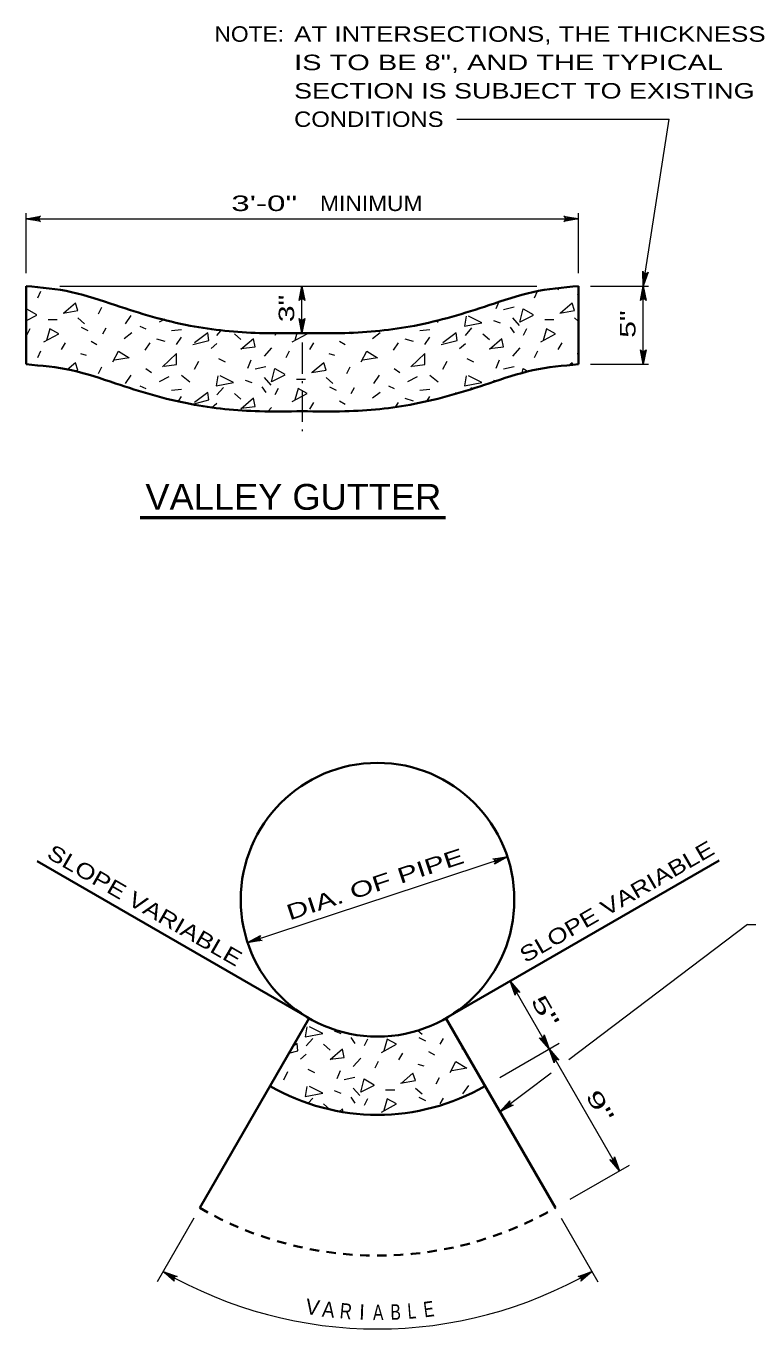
# Model space of a CAD drawing. Extents: x -10 to 104, y -162 to -1.
# Drawn here: x -10.5 to 35.7, y -84.5 to -1.2 of the extents above; entities that cross this region are included whole.
import ezdxf
from ezdxf.enums import TextEntityAlignment as Align

# ---------------------------------------------------------------- set-up
doc = ezdxf.new("R2010")
doc.units = 0
doc.header["$LTSCALE"] = 0.4
doc.linetypes.add('DOT_DASHED', pattern=[7.7, 5, -1.2, 0.3, -1.2])
doc.linetypes.add('SHORT_DASHED', pattern=[2.7, 1.5, -1.2])
for name, color, linetype, lineweight in [('1', 7, 'Continuous', 35), ('10', 7, 'Continuous', 13), ('12', 7, 'Continuous', 53), ('6', 7, 'Continuous', 13)]:
    doc.layers.add(name, color=color, linetype=linetype, lineweight=lineweight)
doc.layers.add('13', color=7, linetype='Continuous')

msp = doc.modelspace()

# ---------------------------------------------------------------- linework, layer by layer
at = {"layer": '1'}
for p, q in [((-10.4681, -17.8014), (-10.4681, -22.8014)), ((24.8652, -17.8014), (24.8652, -22.8014)), ((7.638, -64.6102), (-9.7541, -54.5688)), ((16.388, -64.6102), (33.856, -54.5251)), ((7.638, -64.6102), (0.638, -76.7346)), ((16.388, -64.6102), (23.388, -76.7346))]:
    msp.add_line(p, q, dxfattribs=at)
at = {"layer": '1', "lineweight": 13}
for p, q in [((-6.9918, -18.3044), (-6.6211, -18.4103)), ((6.352, -25.7705), (6.3355, -25.8034)), ((10.8561, -65.7014), (10.8893, -65.7387)), ((13.6282, -70.6866), (13.6428, -70.6632))]:
    msp.add_line(p, q, dxfattribs=at)
for points in [[(17.0503, -24.6252), (17.0481, -24.6056), (17.0049, -24.638), (17.0049, -24.6381)], [(5.1706, -68.9158), (5.3515, -69.0606), (5.3515, -69.0606)]]:
    msp.add_lwpolyline(points, dxfattribs=at)
at = {"layer": '1'}
msp.add_circle((12.013, -57.0325), 8.75, dxfattribs=at)
msp.add_arc((12.013, -57.0325), 13.75, 240, 299.99999, dxfattribs=at)
at = {"layer": '1', "linetype": 'SHORT_DASHED'}
msp.add_arc((12.013, -57.0325), 22.75, 240, 299.99999, dxfattribs=at)
at = {"layer": '1'}
for points in [[(-10.4681, -17.8014), (-7.5503, -18.1833), (-4.7439, -19.0256), (0.0268, -20.336), (4.4702, -20.804), (7.1985, -20.8014)], [(24.8652, -17.8014), (21.9474, -18.1833), (19.141, -19.0256), (14.3702, -20.336), (9.9268, -20.804), (7.1985, -20.8014)], [(-10.4681, -22.8014), (-7.5503, -23.1833), (-4.7439, -24.0256), (0.0268, -25.336), (4.4702, -25.804), (7.1985, -25.8014)], [(24.8652, -22.8014), (21.9474, -23.1833), (19.141, -24.0256), (14.3702, -25.336), (9.9268, -25.804), (7.1985, -25.8014)]]:
    msp.add_spline(points, degree=3, dxfattribs=at)
at = {"layer": '10'}
for p, q in [((17.0886, -7.1328), (30.6672, -7.1328)), ((29.0141, -17.8014), (30.6672, -7.1328)), ((-10.4681, -16.9665), (-10.4681, -13.1495)), ((24.8652, -16.9665), (24.8652, -13.1495)), ((-10.4681, -13.5034), (24.8652, -13.5034)), ((-8.2987, -17.8014), (22.197, -17.8014)), ((7.1827, -20.8014), (7.1799, -17.8014)), ((25.6465, -17.8014), (29.3415, -17.8014)), ((29.0141, -22.8014), (29.0141, -17.8014)), ((25.6465, -22.8014), (29.3415, -22.8014)), ((3.7017, -59.7683), (20.3243, -54.2966)), ((35.6689, -58.6171), (24.2525, -67.2602)), ((35.6689, -58.6171), (51.1348, -58.6171)), ((19.8445, -68.3881), (23.6283, -66.2036)), ((23.1261, -68.1131), (19.8447, -70.5973)), ((24.3445, -76.1824), (28.1283, -73.9978)), ((0.2607, -77.3881), (-2.0887, -81.4574)), ((23.7653, -77.3881), (26.1148, -81.4574))]:
    msp.add_line(p, q, dxfattribs=at)
at = {"layer": '10', "linetype": 'DOT_DASHED'}
msp.add_line((7.1985, -21.4098), (7.2039, -27.0776), dxfattribs=at)
at = {"layer": '10'}
for points in [[(-10.4681, -13.5034), (-9.5361, -13.3286), (-9.6079, -13.3784), (-9.6449, -13.4409), (-9.6556, -13.5034), (-9.6449, -13.5659), (-9.6079, -13.6284), (-9.5361, -13.6781), (-10.4681, -13.5034), (-9.6079, -13.6284), (-9.6449, -13.5659), (-10.4681, -13.5034), (-9.6556, -13.5034), (-9.6449, -13.4409), (-10.4681, -13.5034), (-9.6079, -13.3784)], [(24.8652, -13.5034), (23.9331, -13.6781), (24.0049, -13.6284), (24.042, -13.5659), (24.0527, -13.5034), (24.042, -13.4409), (24.0049, -13.3784), (23.9331, -13.3286), (24.8652, -13.5034), (24.0049, -13.3784), (24.042, -13.4409), (24.8652, -13.5034), (24.0527, -13.5034), (24.042, -13.5659), (24.8652, -13.5034), (24.0049, -13.6284)], [(29.0141, -17.8014), (28.9841, -16.8536), (29.0223, -16.9322), (29.0784, -16.9783), (29.1385, -16.9985), (29.2019, -16.9975), (29.2693, -16.9704), (29.3295, -16.9071), (29.0141, -17.8014), (29.2693, -16.9704), (29.2019, -16.9975), (29.0141, -17.8014), (29.1385, -16.9985), (29.0784, -16.9783), (29.0141, -17.8014), (29.0223, -16.9322)], [(7.1799, -17.8014), (7.3555, -18.7333), (7.3057, -18.6615), (7.2432, -18.6246), (7.1806, -18.6139), (7.1182, -18.6247), (7.0557, -18.6618), (7.006, -18.7336), (7.1799, -17.8014), (7.0557, -18.6618), (7.1182, -18.6247), (7.1799, -17.8014), (7.1806, -18.6139), (7.2432, -18.6246), (7.1799, -17.8014), (7.3057, -18.6615)], [(29.0141, -17.8014), (29.1889, -18.7335), (29.1391, -18.6617), (29.0766, -18.6246), (29.0141, -18.6139), (28.9516, -18.6246), (28.8891, -18.6617), (28.8393, -18.7335), (29.0141, -17.8014), (28.8891, -18.6617), (28.9516, -18.6246), (29.0141, -17.8014), (29.0141, -18.6139), (29.0766, -18.6246), (29.0141, -17.8014), (29.1391, -18.6617)], [(7.1827, -20.8014), (7.0071, -19.8695), (7.0569, -19.9413), (7.1194, -19.9783), (7.1819, -19.9889), (7.2444, -19.9781), (7.3069, -19.9411), (7.3566, -19.8692), (7.1827, -20.8014), (7.3069, -19.9411), (7.2444, -19.9781), (7.1827, -20.8014), (7.1819, -19.9889), (7.1194, -19.9783), (7.1827, -20.8014), (7.0569, -19.9413)], [(29.0141, -22.8014), (28.8393, -21.8693), (28.8891, -21.9412), (28.9516, -21.9782), (29.0141, -21.9889), (29.0766, -21.9782), (29.1391, -21.9412), (29.1889, -21.8693), (29.0141, -22.8014), (29.1391, -21.9412), (29.0766, -21.9782), (29.0141, -22.8014), (29.0141, -21.9889), (28.9516, -21.9782), (29.0141, -22.8014), (28.8891, -21.9412)], [(20.3243, -54.2966), (19.4936, -54.7541), (19.5463, -54.6844), (19.5619, -54.6134), (19.5526, -54.5507), (19.5229, -54.4947), (19.4681, -54.4469), (19.3844, -54.4221), (20.3243, -54.2966), (19.4681, -54.4469), (19.5229, -54.4947), (20.3243, -54.2966), (19.5526, -54.5507), (19.5619, -54.6134), (20.3243, -54.2966), (19.5463, -54.6844)], [(3.7017, -59.7683), (4.5324, -59.3109), (4.4798, -59.3806), (4.4641, -59.4516), (4.4735, -59.5143), (4.5032, -59.5703), (4.5579, -59.6181), (4.6417, -59.6429), (3.7017, -59.7683), (4.5579, -59.6181), (4.5032, -59.5703), (3.7017, -59.7683), (4.4735, -59.5143), (4.4641, -59.4516), (3.7017, -59.7683), (4.4798, -59.3806)], [(27.4926, -74.3648), (22.9926, -66.5706), (20.4926, -62.2405)], [(20.4926, -62.2405), (21.1099, -62.9603), (21.0309, -62.923), (20.9583, -62.9221), (20.8988, -62.9441), (20.85, -62.9846), (20.8144, -63.048), (20.8072, -63.1351), (20.4926, -62.2405), (20.8144, -63.048), (20.85, -62.9846), (20.4926, -62.2405), (20.8988, -62.9441), (20.9583, -62.9221), (20.4926, -62.2405), (21.0309, -62.923)], [(22.9926, -66.5706), (22.3752, -65.8508), (22.4542, -65.8881), (22.5268, -65.8889), (22.5863, -65.8669), (22.6351, -65.8264), (22.6707, -65.7631), (22.6779, -65.676), (22.9926, -66.5706), (22.6707, -65.7631), (22.6351, -65.8264), (22.9926, -66.5706), (22.5863, -65.8669), (22.5268, -65.8889), (22.9926, -66.5706), (22.4542, -65.8881)], [(22.9926, -66.5706), (23.6099, -67.2904), (23.5309, -67.2531), (23.4583, -67.2523), (23.3988, -67.2742), (23.35, -67.3148), (23.3144, -67.3781), (23.3072, -67.4652), (22.9926, -66.5706), (23.3144, -67.3781), (23.35, -67.3148), (22.9926, -66.5706), (23.3988, -67.2742), (23.4583, -67.2523), (22.9926, -66.5706), (23.5309, -67.2531)], [(19.8447, -70.5973), (20.4823, -69.8954), (20.4551, -69.9784), (20.4633, -70.0506), (20.4925, -70.1069), (20.5388, -70.1502), (20.606, -70.1777), (20.6933, -70.174), (19.8447, -70.5973), (20.606, -70.1777), (20.5388, -70.1502), (19.8447, -70.5973), (20.4925, -70.1069), (20.4633, -70.0506), (19.8447, -70.5973), (20.4551, -69.9784)], [(27.4926, -74.3648), (26.8752, -73.645), (26.9542, -73.6823), (27.0268, -73.6831), (27.0863, -73.6612), (27.1351, -73.6206), (27.1707, -73.5573), (27.1779, -73.4702), (27.4926, -74.3648), (27.1707, -73.5573), (27.1351, -73.6206), (27.4926, -74.3648), (27.0863, -73.6612), (27.0268, -73.6831), (27.4926, -74.3648), (26.9542, -73.6823)], [(-1.7064, -80.7953), (-0.8119, -81.11), (-0.899, -81.1172), (-0.9623, -81.1528), (-1.0028, -81.2016), (-1.0248, -81.2611), (-1.024, -81.3337), (-0.9866, -81.4127), (-1.7064, -80.7953), (-1.024, -81.3337), (-1.0248, -81.2611), (-1.7064, -80.7953), (-1.0028, -81.2016), (-0.9623, -81.1528), (-1.7064, -80.7953), (-0.899, -81.1172)], [(25.7325, -80.7953), (25.0127, -81.4127), (25.05, -81.3337), (25.0509, -81.2611), (25.0289, -81.2016), (24.9884, -81.1528), (24.925, -81.1172), (24.838, -81.11), (25.7325, -80.7953), (24.925, -81.1172), (24.9884, -81.1528), (25.7325, -80.7953), (25.0289, -81.2016), (25.0509, -81.2611), (25.7325, -80.7953), (25.05, -81.3337)]]:
    msp.add_lwpolyline(points, dxfattribs=at)
msp.add_arc((12.013, -57.0325), 27.439, 240, 300, dxfattribs=at)
at = {"layer": '12'}
msp.add_line((-3.1772, -32.6017), (16.3578, -32.6017), dxfattribs=at)
at = {"layer": '6'}
for p, q in [((-9.5335, -18.1455), (-9.7453, -18.5691)), ((22.2353, -18.1497), (22.0256, -18.5691)), ((23.5611, -18.0396), (23.6071, -17.9661)), ((24.779, -18.3044), (24.8344, -18.3202)), ((-5.8269, -19.5752), (-5.6151, -19.1516)), ((19.7676, -18.8131), (19.5898, -19.2575)), ((20.7547, -19.1516), (20.0664, -19.3105)), ((-9.7982, -19.6811), (-10.4681, -20.0161)), ((-9.0569, -19.9459), (-8.4744, -19.9459)), ((-7.1506, -19.84), (-6.727, -20.2106)), ((-3.7617, -19.6811), (-4.1324, -20.2106)), ((-1.5885, -19.9183), (-1.9614, -20.1047)), ((15.7351, -19.9862), (15.8832, -20.1047)), ((20.6488, -19.84), (21.0725, -20.3165)), ((22.7139, -19.9459), (23.2964, -19.9459)), ((24.6202, -19.84), (24.8462, -20.0378)), ((-10.2218, -20.5284), (-10.4336, -20.952)), ((-6.9389, -20.4224), (-6.5152, -20.6342)), ((-5.5621, -20.8461), (-5.3503, -20.4754)), ((-3.7088, -20.7931), (-4.1854, -21.1638)), ((-3.1793, -20.3695), (-2.8086, -20.5284)), ((-1.1671, -20.6342), (-0.5317, -20.5813)), ((1.7452, -20.952), (1.9965, -20.6692)), ((5.5263, -20.803), (5.4518, -20.952)), ((6.8563, -20.8017), (6.7226, -21.2697)), ((10.3233, -20.8461), (10.3508, -20.798)), ((12.1766, -20.7931), (11.7, -21.1638)), ((14.7183, -20.6342), (15.3537, -20.5813)), ((17.6306, -20.952), (18.0542, -20.4754)), ((19.431, -19.9988), (19.8546, -20.1577)), ((20.49, -20.4224), (20.7547, -20.7931)), ((21.549, -20.5284), (21.3372, -20.952)), ((24.832, -20.4224), (24.8489, -20.4309)), ((-8.2097, -21.8521), (-7.9449, -21.4285)), ((-6.3034, -21.3226), (-5.9328, -21.5344)), ((-2.5439, -21.4285), (-2.8616, -21.9051)), ((-2.1203, -21.1638), (-1.5907, -21.3226)), ((-0.8494, -21.5344), (-0.5317, -21.0579)), ((1.3745, -21.7992), (1.7452, -21.4815)), ((2.8572, -20.8461), (3.2808, -21.2167)), ((7.6757, -21.8521), (7.9405, -21.4285)), ((9.582, -21.3226), (9.9526, -21.5344)), ((13.3415, -21.4285), (13.0238, -21.9051)), ((13.7651, -21.1638), (14.2947, -21.3226)), ((15.036, -21.5344), (15.3537, -21.0579)), ((17.2599, -21.7992), (17.6306, -21.4815)), ((18.7426, -20.8461), (19.1662, -21.2167)), ((23.5611, -21.8521), (23.8259, -21.4285)), ((-9.5335, -21.958), (-9.7453, -22.3816)), ((-6.9918, -22.1169), (-6.6211, -22.2228)), ((1.8511, -22.4346), (2.2747, -22.6464)), ((5.24, -21.7462), (4.7634, -22.2757)), ((6.352, -21.958), (6.1401, -22.3816)), ((8.8936, -22.1169), (9.2643, -22.2228)), ((17.7365, -22.4346), (18.1601, -22.6464)), ((21.1254, -21.7462), (20.6488, -22.2757)), ((22.2374, -21.958), (22.0256, -22.3816)), ((24.779, -22.1169), (24.8607, -22.1402)), ((-5.8269, -23.3877), (-5.6151, -22.9641)), ((-2.8086, -23.07), (-2.438, -23.3348)), ((0.3155, -23.123), (0.5802, -22.5935)), ((3.9162, -22.5405), (3.7044, -23.07)), ((4.8693, -22.9641), (4.181, -23.123)), ((10.0586, -23.3877), (10.2704, -22.9641)), ((13.0768, -23.07), (13.4474, -23.3348)), ((16.2009, -23.123), (16.4657, -22.5935)), ((19.8016, -22.5405), (19.5898, -23.07)), ((20.7547, -22.9641), (20.0664, -23.123)), ((-3.7617, -23.4936), (-4.1324, -24.0231)), ((-1.326, -23.5995), (-1.9614, -23.9172)), ((-0.5317, -23.4936), (-0.0022, -23.9172)), ((3.5455, -23.8113), (3.9691, -23.9702)), ((4.7634, -23.6525), (5.187, -24.129)), ((6.8285, -23.7584), (7.411, -23.7584)), ((8.7348, -23.6525), (9.1584, -24.0231)), ((12.1237, -23.4936), (11.753, -24.0231)), ((14.5594, -23.5995), (13.924, -23.9172)), ((15.3537, -23.4936), (15.8832, -23.9172)), ((19.431, -23.8113), (19.5977, -23.8739)), ((-3.1793, -24.182), (-2.8086, -24.3409)), ((-1.1671, -24.4467), (-0.5317, -24.3938)), ((-0.7177, -25.1494), (-0.5317, -24.8704)), ((1.7452, -24.7645), (2.1688, -24.2879)), ((2.8572, -24.6586), (3.2808, -25.0292)), ((4.6046, -24.2349), (4.8693, -24.6056)), ((5.6636, -24.3409), (5.4518, -24.7645)), ((8.9466, -24.2349), (9.3702, -24.4467)), ((10.3233, -24.6586), (10.5351, -24.2879)), ((12.1766, -24.6056), (11.7, -24.9763)), ((12.7061, -24.182), (13.0768, -24.3409)), ((13.7651, -24.9763), (14.2947, -25.1351)), ((14.7183, -24.4467), (15.3537, -24.3938)), ((15.1801, -25.1308), (15.3537, -24.8704)), ((17.994, -24.3556), (18.0542, -24.2879)), ((1.3945, -25.5946), (1.7452, -25.294)), ((5.24, -25.5587), (5.0197, -25.8035)), ((7.6757, -25.6646), (7.9405, -25.241)), ((9.582, -25.1351), (9.9526, -25.3469)), ((13.3415, -25.241), (13.1234, -25.5683)), ((15.7608, -64.9974), (15.8008, -64.9175)), ((9.2478, -65.421), (9.6714, -65.5799)), ((14.5883, -65.3946), (14.8607, -65.6329)), ((7.4475, -66.3742), (7.8711, -65.8976)), ((8.5594, -66.2683), (8.9831, -66.6389)), ((10.3068, -65.8446), (10.5716, -66.2153)), ((11.3659, -65.9506), (11.1541, -66.3742)), ((14.6488, -65.8446), (15.0725, -66.0565)), ((16.0256, -66.2683), (16.2374, -65.8976)), ((17.4896, -66.5181), (17.4023, -66.586)), ((7.0768, -67.2214), (7.4475, -66.9037)), ((10.9423, -67.1684), (10.4657, -67.698)), ((12.0542, -67.3803), (11.8424, -67.8039)), ((13.378, -67.2743), (13.6428, -66.8507)), ((15.2843, -66.7448), (15.6549, -66.9566)), ((6.0178, -68.5452), (6.2825, -68.0157)), ((7.5534, -67.8568), (7.977, -68.0686)), ((9.6185, -67.9627), (9.4067, -68.4922)), ((14.5959, -67.5391), (14.9666, -67.645)), ((10.5716, -68.3863), (9.8832, -68.5452)), ((10.4657, -69.0747), (10.8893, -69.5512)), ((14.4371, -69.0747), (14.8607, -69.4454)), ((15.7608, -68.8099), (15.9726, -68.3863)), ((17.8259, -68.9158), (17.4553, -69.4454)), ((7.5748, -70.0434), (7.8711, -69.7101)), ((9.2478, -69.2335), (9.6714, -69.3924)), ((10.3068, -69.6571), (10.5716, -70.0278)), ((11.3659, -69.7631), (11.1541, -70.1867)), ((12.5308, -69.1806), (13.1133, -69.1806)), ((14.6488, -69.6571), (15.0725, -69.869)), ((16.0256, -70.0808), (16.2374, -69.7101)), ((8.5594, -70.0808), (8.9707, -70.4406))]:
    msp.add_line(p, q, dxfattribs=at)
for points in [[(-8.1038, -19.5223), (-7.1506, -19.3634), (-7.3095, -18.8869), (-8.0508, -19.5223)], [(23.6671, -19.5223), (24.6202, -19.3634), (24.4613, -18.8869), (23.72, -19.5223)], [(-10.4681, -19.3955), (-10.4336, -19.2575), (-9.7982, -19.6282)], [(17.6836, -19.7341), (17.5776, -20.3695), (18.6896, -20.1577), (17.8424, -19.7341)], [(21.9726, -19.6811), (21.1254, -20.1047), (21.3372, -19.2575), (21.9726, -19.6282)], [(-9.3217, -21.3756), (-8.3685, -20.8461), (-8.951, -20.5284), (-9.1628, -21.2697)], [(0.2096, -21.5344), (1.2157, -21.2697), (1.1627, -20.7931), (0.3155, -21.4285)], [(6.5637, -21.3756), (7.5169, -20.8461), (7.4357, -20.8018)], [(16.095, -21.5344), (17.1011, -21.2697), (17.0481, -20.7931), (16.2009, -21.4285)], [(22.4492, -21.3756), (23.4023, -20.8461), (22.8198, -20.5284), (22.608, -21.2697)], [(3.2808, -21.7992), (4.181, -21.6933), (4.0751, -21.1638), (3.2808, -21.8521)], [(19.1662, -21.7992), (20.0664, -21.6933), (19.9605, -21.1638), (19.1662, -21.8521)], [(-4.9267, -22.6464), (-4.556, -21.958), (-3.8677, -22.3816), (-4.8208, -22.5405)], [(-1.6437, -22.9112), (-0.8494, -22.8053), (-0.8494, -22.1169), (-1.7496, -22.9641)], [(10.9587, -22.6464), (11.3294, -21.958), (12.0177, -22.3816), (11.0646, -22.5405)], [(14.2417, -22.9112), (15.036, -22.8053), (15.036, -22.1169), (14.1358, -22.9641)], [(-7.4005, -23.2176), (-7.1506, -23.1759), (-7.3095, -22.6994), (-7.8312, -23.1465)], [(6.0872, -23.4936), (5.24, -23.9172), (5.4518, -23.07), (6.0872, -23.4407)], [(7.7816, -23.3348), (8.7348, -23.1759), (8.5759, -22.6994), (7.8346, -23.3348)], [(21.2739, -23.3231), (21.3372, -23.07), (21.6496, -23.2523)], [(24.5108, -22.8478), (24.4613, -22.6994), (24.248, -22.8822)], [(1.7981, -23.5466), (1.6922, -24.182), (2.8042, -23.9702), (1.957, -23.5466)], [(17.6836, -23.5466), (17.5776, -24.182), (18.6896, -23.9702), (17.8424, -23.5466)], [(0.2096, -25.3469), (1.2157, -25.0822), (1.1627, -24.6056), (0.3155, -25.241)], [(3.2808, -25.6117), (4.181, -25.5058), (4.0751, -24.9763), (3.2808, -25.6646)], [(6.5637, -25.1881), (7.5169, -24.6586), (6.9344, -24.3409), (6.7226, -25.0822)], [(7.5004, -65.1563), (7.3945, -65.7917), (8.5065, -65.5799), (7.6593, -65.1563)], [(6.3499, -66.8414), (6.9179, -66.6919), (6.865, -66.2153), (6.594, -66.4186)], [(8.9831, -67.2214), (9.8832, -67.1155), (9.7773, -66.586), (8.9831, -67.2743)], [(12.266, -66.7978), (13.2192, -66.2683), (12.6367, -65.9506), (12.4249, -66.6919)], [(16.661, -68.0686), (17.0317, -67.3803), (17.72, -67.8039), (16.7669, -67.9627)], [(13.4839, -68.757), (14.4371, -68.5981), (14.2782, -68.1216), (13.5369, -68.757)], [(7.5004, -68.9688), (7.3945, -69.6042), (8.5065, -69.3924), (7.6593, -68.9688)], [(11.7895, -68.9158), (10.9423, -69.3394), (11.1541, -68.4922), (11.7895, -68.8629)], [(12.266, -70.6103), (13.2192, -70.0808), (12.6367, -69.7631), (12.4249, -70.5044)], [(9.8188, -70.6056), (9.7773, -70.3985), (9.5855, -70.5648)]]:
    msp.add_lwpolyline(points, dxfattribs=at)

# ---------------------------------------------------------------- texts
at = {"layer": '12'}
for s, width, p in [('NOTE:', 1.1, (1.5841, -2.1828)), ('AT INTERSECTIONS, THE THICKNESS', 1.25, (6.6796, -2.1828)), ('IS TO BE 8", AND THE TYPICAL', 1.4, (6.6796, -3.9978)), ('SECTION IS SUBJECT TO EXISTING', 1.3, (6.6796, -5.8128)), ('CONDITIONS', 1.15, (6.6796, -7.6278))]:
    msp.add_text(s, height=0.99, dxfattribs=dict(at, width=width)).set_placement(p)
for s, height, width, p in [('MINIMUM', 0.99, 1.1, (11.613, -13.0034)), ('VALLEY GUTTER', 1.65, 1.05, (6.6294, -32.1017))]:
    msp.add_text(s, height=height, dxfattribs=dict(at, width=width)).set_placement(p, align=Align.CENTER)
for s, rotation, width, p in [('SLOPE VARIABLE', 30, 1.25, (27.5641, -57.5803)), ('SLOPE VARIABLE', 330, 1.25, (-3.1211, -57.8211)), ('DIA. OF PIPE', 18.22, 1.45, (12.0115, -56.5066)), ('A', 354.557, 0.9, (8.8303, -83.7187)), ('R', 354.557, 0.8, (9.9453, -83.8249)), ('A', 1.105, 0.75, (12.0621, -83.9043)), ('B', 1.105, 0.75, (13.1819, -83.8827)), ('L', 4.379, 0.75, (14.245, -83.808)), ('E', 7.653, 0.75, (15.3552, -83.6927))]:
    msp.add_text(s, height=0.99, rotation=rotation, dxfattribs=dict(at, width=width)).set_placement(p, align=Align.CENTER)
for s, rotation, p in [('V', 351.282, (7.7824, -83.5656)), ('I', 357.831, (11.0031, -83.8813))]:
    msp.add_text(s, height=0.99, rotation=rotation, dxfattribs=at).set_placement(p, align=Align.CENTER)
at = {"layer": '13', "width": 1.6}
msp.add_text('3\'-0"', height=0.99, dxfattribs=at).set_placement((4.7681, -13.0034), align=Align.CENTER)
at = {"layer": '13'}
for s, rotation, width, p in [('3"', 90, 1.45, (6.6813, -19.2318)), ('5"', 90, 1.45, (28.5141, -20.2318)), ('5"', 300, 1.75, (22.3184, -64.403)), ('9"', 300, 1.75, (25.8185, -70.4652))]:
    msp.add_text(s, height=0.99, rotation=rotation, dxfattribs=dict(at, width=width)).set_placement(p, align=Align.CENTER)

doc.saveas('drawing.dxf')
